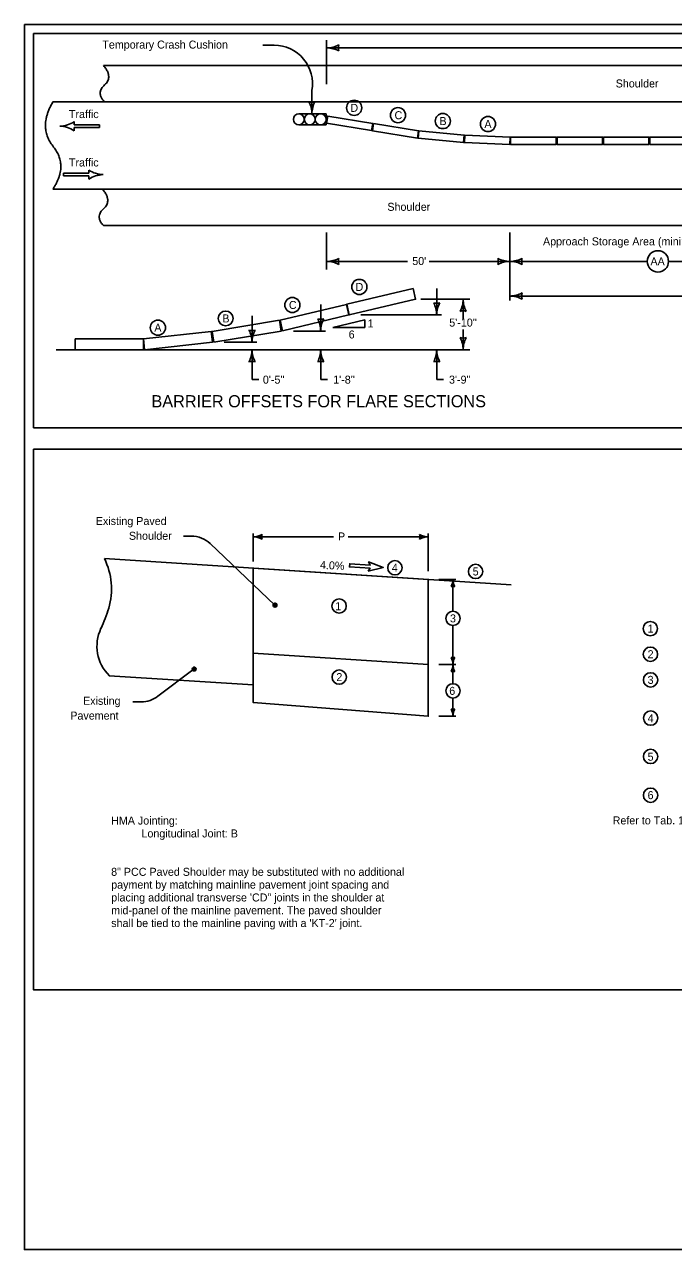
# Model space of a CAD drawing. Extents: x 10133 to 81668, y 5848 to 11018.
# Drawn here: x 13733 to 14802, y 7924 to 9944 of the extents above; entities that cross this region are included whole.
import ezdxf

# ---------------------------------------------------------------- set-up
doc = ezdxf.new("R2010")
doc.units = 0
for name, color, linetype in [('Level 3', 7, 'Continuous'), ('SheetBorder', 7, 'Continuous'), ('SheetText', 7, 'Continuous')]:
    doc.layers.add(name, color=color, linetype=linetype)

msp = doc.modelspace()

# ---------------------------------------------------------------- linework, layer by layer
at = {"layer": 'Level 3'}
msp.add_lwpolyline([(14109.5, 9047.6), (14109.5, 8907.3), (14398, 8888.6), (14398, 9029)], close=True, dxfattribs=at)
at = {"layer": 'SheetBorder'}
msp.add_lwpolyline([(13732.5, 9944), (16867.5, 9944), (16867.5, 7924), (13732.5, 7924)], close=True, dxfattribs=at)
at = {"layer": 'SheetText'}
for p, q in [((13747.5, 9929), (16852.5, 9929)), ((13747.5, 9279), (13747.5, 9929)), ((14143.9, 9909.8), (14125.2, 9909.8)), ((14230.5, 9918.1), (14230.5, 9845.6)), ((14230.5, 9905.4), (15163.3, 9905.4)), ((13862.8, 9876.4), (14991.3, 9876.4)), ((14206.2, 9835.2), (14206.2, 9796.6)), ((13779.2, 9816.4), (15021.3, 9816.4)), ((13814.6, 9783.8), (13814.6, 9778.6)), ((13814.6, 9778.6), (13855.9, 9778.6)), ((13855.9, 9778.6), (13855.9, 9774.1)), ((14184.6, 9796.6), (14229.6, 9796.6)), ((14229.6, 9778.5), (14184.6, 9778.5)), ((14228.4, 9784.3), (14229.7, 9784)), ((14229.6, 9796.6), (14229.6, 9778.5)), ((14230.1, 9780.6), (14230.1, 9780.6)), ((13790.7, 9776.3), (13790.7, 9776.3)), ((13855.9, 9774.1), (13814.6, 9774.1)), ((13814.6, 9774.1), (13814.6, 9768.8)), ((13838.3, 9698.7), (13797, 9698.7)), ((13797, 9698.7), (13797, 9694.2)), ((13838.3, 9704), (13838.3, 9698.7)), ((13862.2, 9696.5), (13862.2, 9696.5)), ((13797, 9694.2), (13838.3, 9694.2)), ((13838.3, 9694.2), (13838.3, 9689)), ((13779.2, 9672.4), (15021.3, 9672.4)), ((13862.8, 9612.4), (14991.3, 9612.4)), ((14230.5, 9601.2), (14230.5, 9539.9)), ((14532.6, 9601.2), (14532.6, 9488.8)), ((14230.5, 9553.4), (14363.9, 9553.4)), ((14399.2, 9553.4), (14532.6, 9553.4)), ((14532.6, 9553.4), (14758.7, 9553.4)), ((14794, 9553.4), (15020.1, 9553.4)), ((14411.9, 9508.5), (14411.9, 9465)), ((14532.6, 9496.3), (15123.4, 9496.3)), ((14220.7, 9482.1), (14220.7, 9438.6)), ((14386, 9491), (14466.4, 9491)), ((14455.5, 9491), (14455.5, 9457.5)), ((14107.5, 9463.5), (14107.5, 9420.1)), ((14240.8, 9444.6), (14293.4, 9457.1)), ((14287, 9465), (14419.7, 9465)), ((14293.4, 9457.1), (14293.4, 9444.6)), ((14175.8, 9438.6), (14228.5, 9438.6)), ((14293.4, 9444.6), (14240.8, 9444.6)), ((14455.5, 9441.2), (14455.5, 9407.7)), ((14061.5, 9420.1), (14115.3, 9420.1)), ((13784.5, 9407.7), (14466.4, 9407.7)), ((14107.5, 9407.7), (14107.5, 9380.8)), ((14220.7, 9407.7), (14220.7, 9358.5)), ((14411.9, 9407.7), (14411.9, 9358.5)), ((14107.5, 9380.8), (14107.5, 9358.5)), ((14107.5, 9358.5), (14118.7, 9358.5)), ((14220.7, 9358.5), (14231.9, 9358.5)), ((14411.9, 9358.5), (14423, 9358.5)), ((16852.5, 9279), (13747.5, 9279)), ((14007.5, 9100.4), (13994.4, 9100.4)), ((14109.5, 9058.6), (14109.5, 9104.8)), ((14109.5, 9099.2), (14241.8, 9099.2)), ((14109.6, 9099.2), (14123.4, 9099.2)), ((14265.7, 9099.2), (14398, 9099.2)), ((14398, 9099.2), (14384.2, 9099.2)), ((14398, 9042.5), (14398, 9104.8)), ((14145.1, 8986.3), (14038.6, 9088)), ((13864.2, 9063.5), (14534.5, 9020.2)), ((14415.3, 9029), (14443.3, 9029)), ((14438.7, 9029), (14438.7, 9017.6)), ((14438.7, 9029), (14438.7, 8976.5)), ((14438.7, 8952.9), (14438.7, 8888.6)), ((14443.3, 8888.6), (14415.3, 8888.6)), ((14438.7, 8888.6), (14438.7, 8900)), ((14438.7, 8888.8), (14438.7, 8877.4)), ((14438.7, 8888.6), (14438.7, 8857)), ((13872.3, 8870.2), (14109.5, 8854.9)), ((13952.4, 8836.4), (14012.4, 8881.4)), ((14438.7, 8833.4), (14438.7, 8803.4)), ((13924.9, 8827.1), (13910.9, 8827.1)), ((14438.7, 8803.4), (14438.7, 8814.8)), ((14443.3, 8803.4), (14415.3, 8803.4))]:
    msp.add_line(p, q, dxfattribs=at)
for points in [[(14306.4, 9781), (14232.4, 9793.1), (14230.5, 9781.3), (14304.5, 9769.1)], [(14381.9, 9768.6), (14307.9, 9780.7), (14306, 9768.9), (14380, 9756.7)], [(14457.3, 9761.4), (14382.7, 9768.5), (14381.5, 9756.5), (14456.2, 9749.4)], [(14533.1, 9758.4), (14458.2, 9761.4), (14457.7, 9749.4), (14532.6, 9746.4)], [(14533.8, 9758.4), (14608.8, 9758.4), (14608.8, 9746.4), (14533.8, 9746.4)], [(14610.3, 9758.4), (14685.3, 9758.4), (14685.3, 9746.4), (14610.3, 9746.4)], [(14686.8, 9758.4), (14761.8, 9758.4), (14761.8, 9746.4), (14686.8, 9746.4)], [(14763.3, 9758.4), (14838.3, 9758.4), (14838.3, 9746.4), (14763.3, 9746.4)], [(14263.5, 9482.6), (14373, 9508.5), (14377.2, 9491), (14267.7, 9465.1)], [(14153.7, 9456.6), (14263.2, 9482.5), (14267.3, 9465), (14157.9, 9439.1)], [(14041.6, 9437.9), (14152.6, 9456.4), (14155.6, 9438.6), (14044.6, 9420.2)], [(13928.5, 9425.6), (14040.4, 9437.9), (14042.3, 9420.1), (13930.5, 9407.7)], [(13816, 9425.9), (13928.5, 9425.7), (13928.5, 9407.7), (13816, 9407.9)], [(13747.5, 9243.6), (15298.3, 9243.6), (15298.3, 8352.2), (13747.5, 8352.2)], [(14298.8, 9042.6), (14323.8, 9048.8), (14299.7, 9057.8), (14302.3, 9052.6), (14268.5, 9054.8), (14268.1, 9049.7), (14302, 9047.5)]]:
    msp.add_lwpolyline(points, close=True, dxfattribs=at)
for points in [[(14123.1, 9096.7), (14122.6, 9099.3), (14123.1, 9101.8), (14120, 9100.4), (14115.1, 9099.3), (14120.4, 9098), (14122.7, 9097), (14122.1, 9099.3), (14122.3, 9100.9), (14120.3, 9099.9), (14117.6, 9099.3), (14120.5, 9098.4), (14122, 9097.9), (14121.7, 9100.1), (14119.7, 9099.3), (14121.3, 9098.8), (14121.3, 9099.5), (14120.6, 9099.3)], [(14384.5, 9101.8), (14385, 9099.2), (14384.5, 9096.6), (14387.6, 9098.1), (14392.5, 9099.2), (14387.2, 9100.5), (14384.9, 9101.5), (14385.5, 9099.2), (14385.3, 9097.6), (14387.3, 9098.5), (14390, 9099.2), (14387.1, 9100.1), (14385.6, 9100.6), (14385.9, 9098.4), (14387.9, 9099.2), (14386.3, 9099.7), (14386.3, 9099), (14387, 9099.2)], [(14109.5, 9047.9), (14109.5, 8826), (14398, 8803.4), (14398, 9029)], [(14436.6, 9017.8), (14438.7, 9018.2), (14440.9, 9017.8), (14439.6, 9020.3), (14438.7, 9024.4), (14437.7, 9020), (14436.9, 9018.1), (14438.7, 9018.6), (14440.1, 9018.4), (14439.3, 9020.1), (14438.7, 9022.4), (14438, 9020), (14437.6, 9018.7), (14439.4, 9018.9), (14438.7, 9020.6), (14438.3, 9019.3), (14438.9, 9019.3), (14438.7, 9019.9)], [(14147.7, 8988.4), (14146.6, 8988.8), (14145, 8989.6), (14143.6, 8988.7), (14142.7, 8987.5), (14142.5, 8985.8), (14143.7, 8984.7), (14145.1, 8983.7), (14146.6, 8984.1), (14147.7, 8985), (14148.3, 8987), (14147.5, 8987.9), (14146, 8988.8), (14144.3, 8989), (14143.2, 8987.9), (14143.1, 8986.2), (14144.1, 8985.1), (14145.5, 8984.1), (14146.3, 8984.6), (14147.3, 8985.2), (14147.7, 8986.7), (14146.9, 8987.5), (14145.7, 8988.3), (14144.5, 8988.5), (14143.9, 8987.2), (14144, 8985.9), (14145, 8984.9), (14145.8, 8985.1), (14146.7, 8985.4), (14147, 8986.7), (14146.4, 8987.6), (14145.4, 8987.9), (14144.6, 8987.2), (14144.5, 8986.3), (14145, 8985.5), (14145.5, 8985.5), (14146.1, 8985.7), (14146.4, 8986.6), (14146, 8987.2), (14145.3, 8987.3), (14145, 8986.9), (14145.1, 8986.3), (14145.5, 8985.9), (14145.9, 8986.2), (14145.6, 8986.8)], [(14440.8, 8899.8), (14438.7, 8899.4), (14436.5, 8899.8), (14437.8, 8897.3), (14438.7, 8893.2), (14439.7, 8897.6), (14440.5, 8899.4), (14438.7, 8899), (14437.3, 8899.2), (14438.1, 8897.5), (14438.7, 8895.2), (14439.4, 8897.6), (14439.8, 8898.9), (14438, 8898.6), (14438.7, 8897), (14439.1, 8898.3), (14438.5, 8898.3), (14438.7, 8897.7)], [(14014.4, 8883), (14013.3, 8883.5), (14011.8, 8884.3), (14010.4, 8883.3), (14009.5, 8882.1), (14009.3, 8880.4), (14010.5, 8879.4), (14011.8, 8878.4), (14013.3, 8878.7), (14014.4, 8879.6), (14015, 8881.6), (14014.3, 8882.6), (14012.8, 8883.4), (14011.1, 8883.7), (14010, 8882.5), (14009.9, 8880.9), (14010.8, 8879.7), (14012.2, 8878.8), (14013.1, 8879.3), (14014.1, 8879.8), (14014.5, 8881.3), (14013.6, 8882.2), (14012.5, 8883), (14011.2, 8883.1), (14010.6, 8881.8), (14010.8, 8880.5), (14011.7, 8879.5), (14012.5, 8879.8), (14013.4, 8880.1), (14013.7, 8881.3), (14013.2, 8882.2), (14012.2, 8882.5), (14011.4, 8881.8), (14011.2, 8881), (14011.7, 8880.1), (14012.3, 8880.1), (14012.9, 8880.3), (14013.1, 8881.2), (14012.8, 8881.8), (14012.1, 8882), (14011.7, 8881.5), (14011.8, 8880.9), (14012.3, 8880.5), (14012.6, 8880.8), (14012.4, 8881.4)], [(14436.6, 8877.7), (14438.7, 8878.1), (14440.9, 8877.6), (14439.6, 8880.2), (14438.7, 8884.3), (14437.7, 8879.9), (14436.9, 8878), (14438.7, 8878.5), (14440.1, 8878.3), (14439.3, 8880), (14438.7, 8882.2), (14438, 8879.8), (14437.6, 8878.6), (14439.4, 8878.8), (14438.7, 8880.5), (14438.3, 8879.2), (14438.9, 8879.2), (14438.7, 8879.8)], [(14440.8, 8814.6), (14438.7, 8814.2), (14436.5, 8814.6), (14437.8, 8812.1), (14438.7, 8808), (14439.7, 8812.4), (14440.5, 8814.2), (14438.7, 8813.8), (14437.3, 8814), (14438.1, 8812.3), (14438.7, 8810), (14439.4, 8812.4), (14439.8, 8813.7), (14438, 8813.4), (14438.7, 8811.8), (14439.1, 8813.1), (14438.5, 8813.1), (14438.7, 8812.5)]]:
    msp.add_lwpolyline(points, dxfattribs=at)
for centre, radius in [((14275.9, 9806.6), 12.5), ((14348.1, 9794.4), 12.5), ((14421.9, 9784.8), 12.5), ((14184.6, 9787.6), 9), ((14184.6, 9787.6), 9), ((14202.6, 9787.6), 9), ((14202.6, 9787.6), 9), ((14220.6, 9787.6), 9), ((14220.6, 9787.6), 9), ((14496.4, 9779.9), 12.5), ((14776.4, 9553.4), 17.6), ((14284.4, 9511.3), 12.5), ((14174, 9481.5), 12.5), ((13952.4, 9444.1), 12.5), ((14064, 9459.3), 12.2), ((14343, 9048.2), 11.8), ((14476, 9042.1), 11.8), ((14145.4, 8986.5), 3.15), ((14251.1, 8985.1), 11.8), ((14438.7, 8964.7), 11.8), ((14764, 8947.8), 11.8), ((14764.2, 8905.6), 11.8), ((14012.2, 8881.2), 3.15), ((14251.2, 8867.9), 11.8), ((14764.4, 8863.3), 11.8), ((14438.7, 8845.2), 11.8), ((14764.6, 8800.3), 11.8), ((14764.4, 8737), 11.8), ((14764.4, 8673.1), 11.8)]:
    msp.add_circle(centre, radius, dxfattribs=at)
for centre, radius, start, end in [((14143.9, 9846.5), 63.3, 349.6463, 90), ((14230.5, 9947.9), 42.5, 270, 298.0725), ((14230.5, 9862.9), 42.5, 61.9275, 90), ((14266.1, 9905.4), 16.4, 162.2666, 197.7334), ((14206.2, 9832.2), 16.4, 252.2666, 287.7333), ((14163.7, 9796.6), 42.5, 360, 28.0725), ((14248.7, 9796.6), 42.5, 151.9275, 180), ((13788.7, 9824.6), 48.4, 272.352, 302.382), ((13788.7, 9728), 48.4, 57.618, 87.648), ((13864.2, 9744.8), 48.4, 237.618, 267.648), ((13864.2, 9648.1), 48.4, 92.352, 122.382), ((14230.5, 9595.9), 42.5, 270, 298.0725), ((14266.1, 9553.4), 16.4, 162.2666, 197.7334), ((14497, 9553.4), 16.4, 342.2666, 17.7333), ((14532.6, 9595.9), 42.5, 241.9275, 270), ((14532.6, 9595.9), 42.5, 270, 298.0725), ((14568.3, 9553.4), 16.4, 162.2666, 197.7334), ((14230.5, 9510.9), 42.5, 61.9275, 90), ((14532.6, 9510.9), 42.5, 90, 118.0725), ((14532.6, 9510.9), 42.5, 61.9275, 90), ((14532.6, 9538.8), 42.5, 270, 298.0725), ((14532.6, 9453.8), 42.5, 61.9275, 90), ((14568.3, 9496.3), 16.4, 162.2666, 197.7334), ((14411.9, 9500.7), 16.4, 252.2666, 287.7333), ((14369.4, 9465), 42.5, 360, 28.0725), ((14454.4, 9465), 42.5, 151.9275, 180), ((14413, 9491), 42.5, 331.9275, 360), ((14498, 9491), 42.5, 180, 208.0725), ((14220.7, 9474.3), 16.4, 252.2666, 287.7333), ((14178.2, 9438.6), 42.5, 360, 28.0725), ((14263.2, 9438.6), 42.5, 151.9275, 180), ((14455.5, 9455.4), 16.4, 72.2666, 107.7334), ((14107.5, 9455.7), 16.4, 252.2666, 287.7333), ((14065, 9420.1), 42.5, 360, 28.0725), ((14150, 9420.1), 42.5, 151.9275, 180), ((14455.5, 9443.4), 16.4, 252.2666, 287.7333), ((14413, 9407.7), 42.5, 360, 28.0725), ((14498, 9407.7), 42.5, 151.9275, 180), ((14065, 9407.7), 42.5, 331.9275, 360), ((14150, 9407.7), 42.5, 180, 208.0725), ((14178.2, 9407.7), 42.5, 331.9275, 360), ((14263.2, 9407.7), 42.5, 180, 208.0725), ((14369.4, 9407.7), 42.5, 331.9275, 360), ((14454.4, 9407.7), 42.5, 180, 208.0725), ((14107.5, 9372.1), 16.4, 72.2666, 107.7334), ((14220.7, 9372.1), 16.4, 72.2666, 107.7334), ((14411.9, 9372.1), 16.4, 72.2666, 107.7334), ((14007.5, 9055.4), 45, 46.3216, 90), ((14109.6, 9129.8), 30.6, 270, 298.0725), ((14109.6, 9068.6), 30.6, 61.9275, 90), ((14135.2, 9099.2), 11.8, 162.2666, 197.7334), ((14372.4, 9099.2), 11.8, 342.2666, 17.7334), ((14398, 9129.8), 30.6, 241.9275, 270), ((14398, 9068.6), 30.6, 90, 118.0725), ((13762.9, 9013.4), 113, 343.6708, 26.3373), ((14413.5, 9029), 25.2, 331.9275, 360), ((14438.7, 9007.8), 9.75, 72.2666, 107.7334), ((14463.9, 9029), 25.2, 180, 208.0725), ((13658.9, 9043.9), 221.4, 334.4332, 343.6708), ((13920.1, 8918.9), 68.2, 154.4332, 225.5564), ((14438.7, 8909.8), 9.75, 252.2666, 287.7334), ((14413.5, 8888.6), 25.2, 360, 28.0725), ((14413.5, 8888.8), 25.2, 331.9275, 360), ((14463.9, 8888.6), 25.2, 151.9275, 180), ((14463.9, 8888.8), 25.2, 180, 208.0725), ((14438.7, 8867.7), 9.75, 72.2666, 107.7334), ((13924.9, 8872.1), 45, 270, 307.6187), ((14438.7, 8824.6), 9.75, 252.2666, 287.7334), ((14413.5, 8803.4), 25.2, 360, 28.0725), ((14463.9, 8803.4), 25.2, 151.9275, 180)]:
    msp.add_arc(centre, radius, start, end, dxfattribs=at)
for points in [[(13862.8, 9876.4), (13878.9, 9857.1), (13850, 9831.5), (13864.4, 9816.5)], [(13779.2, 9816.4), (13754.6, 9773.8), (13805.3, 9711.6), (13779.2, 9672.4)], [(13861.2, 9672.4), (13877.3, 9653.1), (13848.4, 9627.5), (13862.8, 9612.4)]]:
    msp.add_open_spline(points, degree=2, dxfattribs=at)

# ---------------------------------------------------------------- texts
for s, height, p in [('Temporary Crash Cushion', 13.2, (13860.8, 9904.3)), ('Shoulder', 13.2, (14706.9, 9840.2)), ('Traffic', 13.2, (13805.7, 9789.7)), ('D', 13.2, (14269.6, 9800)), ('C', 13.2, (14342.4, 9787.8)), ('B', 13.2, (14416.4, 9778.2)), ('A', 13.2, (14490.5, 9773.3)), ('Traffic', 13.2, (13805.7, 9709.9)), ('Shoulder', 13.2, (14330.6, 9636.8)), ("Approach Storage Area (minimum 20')", 13.2, (14587.1, 9579.8)), ("50'", 13.2, (14371.6, 9547.4)), ('AA', 13.2, (14764.2, 9546.8)), ('D', 13.2, (14278.1, 9504.7)), ('C', 13.2, (14168.3, 9474.9)), ('B', 13.2, (14058.6, 9452.7)), ('1', 13.2, (14298.1, 9444.4)), ("5'-10''", 13.2, (14432.6, 9445.9)), ('A', 13.2, (13946.5, 9437.5)), ('6', 13.2, (14266.8, 9426.3)), ("0'-5''", 13.2, (14125.4, 9351.8)), ("1'-8''", 13.2, (14241.3, 9351.8)), ("3'-9''", 13.2, (14432.2, 9351.8)), ('BARRIER OFFSETS FOR FLARE SECTIONS', 20, (13941.8, 9312.8)), ('Existing Paved', 13.2, (13850, 9118.7)), ('Shoulder', 13.2, (13904.6, 9094.3)), ('P', 13.2, (14249.2, 9093.2)), ('4', 13.2, (14337.9, 9041.6)), ('5', 13.2, (14471.2, 9035.5)), ('1', 13.2, (14244.6, 8978.2)), ('3', 13.2, (14433.8, 8958.1)), ('1', 13.2, (14759.5, 8941.2)), ('2', 13.2, (14759.5, 8899)), ('2', 13.2, (14246.5, 8861.3)), ('3', 13.2, (14759.5, 8856.7)), ('6', 13.2, (14432.6, 8838.6)), ('Existing', 13.2, (13829, 8822.2)), ('Pavement', 13.2, (13808, 8797.8)), ('4', 13.2, (14759.5, 8793.4)), ('5', 13.2, (14759.5, 8730)), ('6', 13.2, (14759.5, 8666.6)), ('HMA Jointing:', 13.2, (13875.3, 8624.7)), ('Refer to Tab. 112-9 for P width and Shoulder quantities', 13.2, (14701.9, 8625)), ('Longitudinal Joint: B', 13.2, (13925.3, 8603.5)), ('8" PCC Paved Shoulder may be substituted with no additional ', 13.2, (13875.3, 8540.2)), ('payment by matching mainline pavement joint spacing and ', 13.2, (13875.4, 8519.1)), ('placing additional transverse \'CD" joints in the shoulder at ', 13.2, (13875.4, 8497.9)), ('mid-panel of the mainline pavement. The paved shoulder ', 13.2, (13875.4, 8476.8)), ("shall be tied to the mainline paving with a 'KT-2' joint.", 13.2, (13875.4, 8455.7))]:
    msp.add_text(s, height=height, dxfattribs=at).set_placement(p)
msp.add_text('4.0%', height=13.2, rotation=357.4961, dxfattribs=at).set_placement((14219.3, 9046.4))

doc.saveas('drawing.dxf')
